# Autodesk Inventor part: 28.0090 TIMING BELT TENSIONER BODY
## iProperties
Created: 2007-04
Part Number: 28.0090 TIMING BELT TENSIONER BODY
Document SubType Name: Modeling
Designer: Andy Moles
Material: Aluminum-6061
Mass: 131.399 g
Surface Area: 190.589 cm^2
Volume: 48.4868 cm^3
Density: 2.71 g/cm^3
Author: Andy Moles
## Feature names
1. Extrusion1
2. Hole1
3. Hole2
4. Extrusion2
5. Extrusion3
6. Extrusion4
7. Extrusion5
